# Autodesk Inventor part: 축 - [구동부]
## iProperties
Company: 한국ATC센터
Created: 2014-08
Part Number: 축 - [구동부]
Document SubType Name: Modeling
Designer: KYOUNG IL JANG
Density: 1 g/cm^3
Author: KYOUNG IL JANG
